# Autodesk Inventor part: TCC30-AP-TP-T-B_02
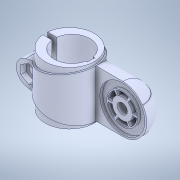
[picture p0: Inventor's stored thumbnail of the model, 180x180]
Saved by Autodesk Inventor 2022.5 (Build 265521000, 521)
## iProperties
Created: 2023-09
Part Number: TCC30-AP-TP-T-B_02
Material: 一般
Document SubType Name: Modeling
Designer: ImaoCorp
Density: 1 g/cm^3
Appearance: 既定
Author: ImaoCorp
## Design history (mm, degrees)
feature "TCC30-AP-TP-T-B_02"
node "ソリッド1"
